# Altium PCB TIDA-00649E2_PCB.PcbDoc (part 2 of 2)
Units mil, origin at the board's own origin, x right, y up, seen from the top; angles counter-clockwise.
Board outline 3905 x 2600 mil, 2 copper layers (Top Layer, Bottom Layer), stack 62 mil thick; 120 components, 45 nets, 260 pads, 117 vias.
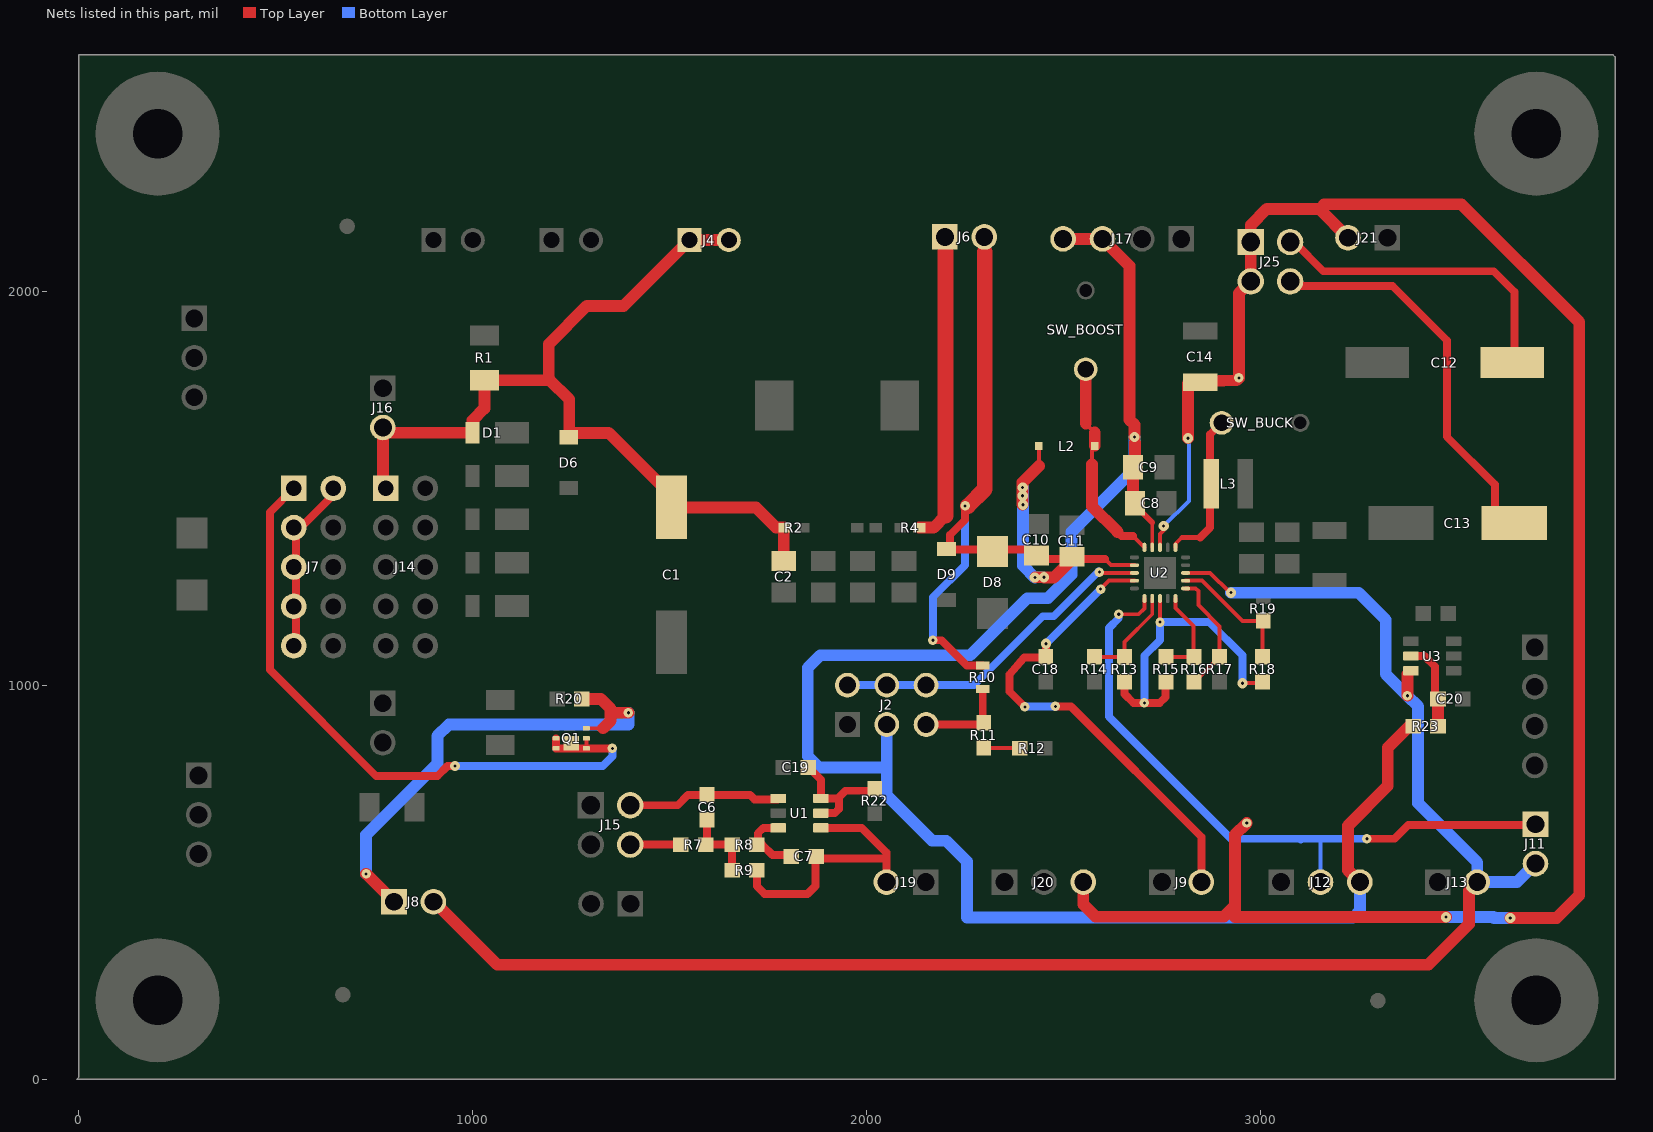
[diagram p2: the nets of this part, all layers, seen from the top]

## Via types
v1: diameter 24, hole 8, Top Layer to Bottom Layer, tented both sides, 66 vias
v2: diameter 26, hole 8, Top Layer to Bottom Layer, tented both sides, 47 vias
v3: diameter 19.68, hole 7.87, Top Layer to Bottom Layer, 4 vias

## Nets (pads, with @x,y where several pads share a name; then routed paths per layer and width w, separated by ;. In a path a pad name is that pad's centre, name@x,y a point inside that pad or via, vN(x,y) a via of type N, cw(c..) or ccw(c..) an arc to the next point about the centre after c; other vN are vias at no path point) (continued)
NetC6_1: C6.1 J15.2 U1.1 | length 389.2
  Top Layer w20: J15.2@1399.68,695 1520,695 1546.5,721.5 C6.1@1594.68,721.5 1703.5,721.5 1715,710 U1.1@1773.15,710
NetC6_2: C6.2 R7.2 R8.1 R9.1 | length 190
  Top Layer w10: R7.2@1594.68,598.5 R7.2@1598.19,595
  Top Layer w20: R7.2@1594.68,598.5 C6.2@1594.68,658.5 ; R7.2@1598.19,595 R8.1@1658.19,595 R9.1@1658.19,530
NetC7_1: C7.1 J19.2 R9.2 U1.4 | length 721.9
  Top Layer w20: R9.2@1721.18,530 1721.18,489.82 1741,470 1850,470 1870,490 1870,558.82 1871.18,560 2050,560 ; U1.4@1883.82,637.6 1987.4,637.6 2050,575 J19.2@2050,500
NetC7_2: C7.2 R8.2 U1.3 | length 185.3
  Top Layer w20: R8.2@1721.18,595 1735,595 1761,569 1799.19,569 C7.2@1808.19,560 ; R8.2@1723.68,597.5 1723.68,623.68 1737.6,637.6 U1.3@1775.55,637.6
NetC10_1: C10.1 C11.1 D8.1 D9.1 J6.2 L2.1 R10.1 U2.2 | length 2358.3
  Top Layer w10: 2437.13,1556.13 L2.1@2437.13,1607 L2.1@2437.13,1608 ; C11.1@2519.68,1317.68 C11.1@2519.68,1318.69 ; 2605,1320 2620.32,1304.68 U2.2@2679.72,1304.68
  Top Layer w20: v1(2168,1114) 2190,1114 2254,1050 R10.1@2294.68,1050 ; v1(2250,1455) 2250,1420 2212,1382 2212,1344 2412.71,1344 C10.1@2431,1325.71 ; C10.1@2413,1320 2605,1320
  Top Layer w30: v2@2396,1459 v2(2396,1481) v2(2396,1502) 2396,1515 2437.13,1556.13 ; v2@2428,1274 v2(2450,1274) ; v2@2450,1273 2475,1273 C11.1@2519.68,1317.68
  Top Layer w40: v1@2257,1455 2299.68,1497.68 2299.68,2100
  Bottom Layer w20: v1(2168,1114) 2168,1223.12 2250,1305.12 v1(2250,1455)
  Bottom Layer w30: v2@2397,1501 v2(2397,1458) 2397,1303 v2(2427,1273) 2428,1274 v2(2450,1274)
NetC12_1: C12.1 J25.2 | length 829.3
  Top Layer w20: J25.2@3075,2125 3085.43,2125 3159.43,2051 3592,2051 3644.26,1998.74 C12.1@3644.26,1791
NetC13_1: C13.1 J25.4 | length 1003.5
  Top Layer w20: J25.4@3075,2025 3087,2013 3335.37,2013 3473,1875.37 3473,1631 3595,1509 3595,1447.73 C13.1@3641.22,1401.51
NetC19_2: C19.2 R22.1 U1.5 U1.6 | length 319.7
  Top Layer w20: C19.2@1852.62,791.14 1883.82,759.94 U1.6@1883.82,712.4 1926.4,712.4 ; U1.5@1883.82,675 1919,675 1930,686 1930,712.4 1926.4,712.4 ; R22.1@2020.73,737.48 2015.24,732 1946,732 1926.4,712.4
NetC20_1: C20.1 R23.2 U3.5 | length 210.3
  Top Layer w20: U3.5@3381.87,1074 3416.31,1074 3442.5,1047.81 C20.1@3442.5,978
  Top Layer w30: R23.2@3450.5,896 C20.1@3450.5,965
NetJ2_2: J2.2 J2.4 J2.6 U2.3 | length 847.3
  Top Layer w10: v1@2593,1285 U2.3@2679.72,1285
  Bottom Layer w10: v1@2589,1289 v1(2591,1287)
  Bottom Layer w20: J2.2@1950.98,1000 J2.4@2050.98,1000 J2.6@2150.98,1000 2272,1000 2447,1175 2475,1175 v1@2589,1289
NetJ2_5: J2.5 R10.2 R11.2 | length 224.7
  Top Layer w20: J2.5@2150.98,900 R11.2@2292.5,900 ; R11.2@2294.68,906.81 R10.2@2294.68,990
NetJ7_1: J7.1 Q1.1 Q1.2 Q1.5 Q1.6 Q1.8 | length 1702.2
  Top Layer w10: Q1.1@1288.39,839.41 Q1.2@1288.39,865
  Top Layer w20: J7.1@545.68,1500 545.68,1499.68 485,1439 485,1039 755,769 910,769 936,795 v2(955,795) ; Q1.5@1211.62,865 Q1.6@1211.62,839.41 Q1.1@1288.39,839.41 v1(1354.41,839.41)
  Bottom Layer w20: v2(955,795) 1330,795 1354.41,819.41 v1(1354.41,839.41)
NetJ8_1: J8.1 Q1.3 R20.2 | length 1280.6
  Top Layer w10: Q1.3@1288.39,890.59 1330.59,890.59
  Top Layer w30: v1(729,521) J8.1@800,450 ; R20.2@1276.81,965 1325,965 1350,940 1350,930 ; 1330.59,890.59 1350,910 1350,930 ; v1(1395,930) 1350,930
  Bottom Layer w30: v1(729,521) 729,620 910,801 910,871 939,900 1395,900 v1(1395,930)
NetJ15_4: J15.4 R7.1 | length 128.5
  Top Layer w20: J15.4@1399.68,595 R7.1@1528.19,595
NetL2_2: L2.2 SW_BOOST.1 U2.20 | length 536.7
  Top Layer w10: 2556,1664 2578.87,1641.13 ; 2572,1561 2572,1601.13 L2.2@2578.87,1608 ; 2637,1389 2647,1379 ; 2676.28,1379 U2.20@2705.31,1349.96
  Top Layer w20: 2647,1379 2676.28,1379
  Top Layer w30: 2556,1664 SW_BOOST.1@2556,1802 ; 2572,1561 2572,1454 2637,1389 ; L2.2@2578.87,1608 2578.87,1641.13
NetL3_1: L3.1 SW_BUCK.1 U2.16 | length 392
  Top Layer w10: U2.16@2784.06,1349.96 2784.06,1359.06 2800,1375
  Top Layer w12: 2800,1375 2847,1375
  Top Layer w20: 2847,1375 2872,1400 2872,1637 SW_BUCK.1@2901,1666
NetR11_1: R11.1 R12.1 | length 90
  Top Layer w10: R11.1@2298.5,840 R12.1@2388.5,840
NFET: J7.2 J7.3 J7.5 J7.7 J7.9 | length 441.4
  Top Layer w20: J7.9@550.68,1110 550.68,1387.68 650.68,1487.68 J7.2@650.68,1510
OK_HYST: R15.1 R16.2 U2.10 | length 237.6
  Top Layer w10: R15.1@2760,1071.5 R16.2@2831.19,1071.5 ; U2.10@2784.06,1220.04 2784.06,1195.94 2830,1150 R16.2@2830,1072.68
OK_PROG: R16.1 R17.2 U2.11 | length 315.9
  Top Layer w10: U2.11@2809.65,1245.63 2835.37,1245.63 2842,1239 2842,1203 2896,1149 R17.2@2896,1071.5 2833.01,1008.5 R16.1@2831.19,1008.5
V_FILTER_OUT: J6.1 R4.2 | length 748.8
  Top Layer w30: R4.2@2133.31,1400 2170,1400 2200,1430
  Top Layer w40: 2200,1430 2200,2099.68
VBAT: C14.2 J20.3 J21.2 J25.1 J25.3 U2.18 | length 5097.9
  Top Layer w10: U2.18@2744.68,1349.96 2744.68,1383.68 2754,1393 v2(2754,1404) ; 3149,2209 3161,2221
  Top Layer w30: 2550,443 J20.3@2550,500 ; 2552,441 2581,412 2907,412 2935,440 ; v2(2816,1627) C14.2@2816,1766 ; C14.2@2847,1771.01 2939.04,1774.04 v1(2945,1780) 2945,1995 J25.3@2975,2025 J25.1@2975,2125 2975,2168 3016,2209 3149,2209 J21.2@3222,2136 ; v1(2965,650) 2935,620 2935,411 v2(3471,411) ; 3161,2221 3510,2221 3809,1922 3809,466 3752,409 v2(3634,409)
  Bottom Layer w10: v2(2754,1404) 2818,1468 v2@2818,1625
  Bottom Layer w30: v2(3471,411) 3591,411 3593,409 v2(3634,409)
VBAT_OK: J8.2 J11.2 J13.2 U2.13 U3.6 | length 4405.6
  Top Layer w10: U2.13@2809.65,1285 2872,1285 2922.16,1234.84 v2(2924.72,1234.84)
  Top Layer w30: J8.2@900,450 895,445 907,445 1062,290 3426,290 3529,393 3529,479 J13.2@3550,500 ; v1(3373,973) U3.6@3373,1027.73
  Bottom Layer w30: v2(2924.72,1234.84) 3249.16,1234.84 3318,1166 3318,1028 v1(3373,973) 3400,946 3400,700 3550,550 J13.2@3550,500 3651,500 J11.2@3698,547
VBAT_OV: R13.2 R14.1 U2.7 | length 254.2
  Top Layer w10: R14.1@2578.18,1071.5 R13.2@2654.68,1071.5 2654.68,1109.68 2725,1180 U2.7@2725,1220.04
VD: C1.1 C2.1 D1.2 D6.1 J4.1 J4.2 J14.1 J16.2 R1.1 R2.1 | length 2234.5
  Top Layer w30: J14.1@771.68,1504.31 J16.2@771.68,1654 ; J16.2@784.68,1641 D1.2@999.49,1641 999.49,1672.49 1029.68,1702.68 R1.1@1029.68,1773.91 1192.6,1773.91 1192.6,1866 1289.6,1963 1383,1963 J4.1@1550,2130 J4.2@1650,2130 ; 1194.68,1776 1244.68,1726 1244.68,1640.47 1344.53,1640.47 1504.68,1480.32 C1.1@1504.68,1451.26 1718.74,1451.26 1770,1400 R2.1@1791.38,1400 ; C2.1@1789.68,1315 R2.1@1789.68,1398.31
VOUT_EN: J11.1 J12.2 U2.6 | length 1762.2
  Top Layer w10: v1(2640,1180) 2690,1180 2705,1195 2705,1219.72 U2.6@2705.31,1220.04 U2.6@2705.31,1209.25
  Top Layer w20: v1(3270,610) 3340,610 3375,645 J11.1@3696,645
  Bottom Layer w10: v1@2640,1170 v1(2640,1180) ; 3100,610 3147,610 3152.2,604.8 J12.2@3152.2,500
  Bottom Layer w20: v1@2640,1170 2615,1145 2615,920 2925,610 3100,610 3102,608 3104,610 v1(3270,610)
VOUT_SET: R18.1 R19.2 U2.12 | length 331.2
  Top Layer w10: U2.12@2809.65,1265.31 2851.68,1265.31 2903.44,1213.56 2953.99,1163.01 R19.2@3005,1163.01 ; R18.1@3005,1071.5 R19.2@3005,1163.01 ; R19.2@3007,1163.01 R19.2@3005,1163.01
VRDIV: R13.1 R15.2 R18.2 U2.8 | length 832.5
  Top Layer w10: v1(2744.68,1160) U2.8@2744.68,1220.04 ; v2(2954,1005) R18.2@3001.5,1005
  Top Layer w20: R13.1@2654.68,1008.5 2654.68,977.32 2677,955 v1(2705,955) 2744,955 2759,970 R15.2@2759,1007.5
  Bottom Layer w20: v1(2705,955) 2705,1074.63 2744.68,1114.32 v1(2744.68,1160) 2870,1160 2954,1076 v2(2954,1005)
VREF_SAMP: C18.1 J9.2 U2.4 | length 1233.8
  Top Layer w10: v1(2594,1244) 2615.31,1265.31 U2.4@2679.72,1265.31
  Top Layer w20: v1(2401.57,944.88) 2362.2,984.25 2362.2,1027.2 2400,1070 C18.1@2453.19,1070 ; C18.1@2455,1071.81 v2(2455,1105) ; v1(2479,946) 2518.57,946 2849.68,614.88 J9.2@2849.68,500
  Bottom Layer w20: v1(2401.57,944.88) 2402.69,946 v1(2479,946) ; v2(2455,1105) v1(2594,1244)
VSTOR: C8.1 C9.1 J2.3 J12.3 J17.3 J17.4 R23.1 U2.19 | length 4702.8
  Top Layer w10: U2.19@2725,1349.96 2725,1413
  Top Layer w15: C8.1@2676,1462 2725,1413
  Top Layer w30: J17.4@2498.68,2133 J17.3@2598.68,2133 2667,2064.68 2667,1674 2680,1661 v2(2680,1630) ; C9.1@2674,1542 C9.1@2676,1544 ; C8.1@2675.31,1448.54 C8.1@2676,1447.85 ; C8.1@2676,1462 C9.1@2676,1544 ; C9.1@2676,1553 C9.1@2676,1544 ; C9.1@2681,1553 2681,1616 ; J12.3@3252.2,500 3222,530.19 3222,643 3323,744 3323,841.5 3377.5,896 R23.1@3387.5,896
  Bottom Layer w30: J2.3@2050.98,900 2050.98,791.14 ; v2(2680,1630) 2680,1549 2519.68,1388.68 2519.68,1280.16 2460,1220.47 2407.47,1220.47 2263,1076 1882,1076 1850.39,1044.39 1850.39,819.61 1878.86,791.14 2050.98,791.14 ; J12.3@3252.2,500 3252.2,427.19 3235,410 2255,410 2255,552 2202,605 2166,605 2050.98,720.02 2050.98,791.14
pads on no net: FID1.1 FID2.1 FID3.1 H1.1 H2.1 H3.1 H4.1 Q1.0 SH-J1.0 SH-J2.0 SH-J3.0 SH-J4.0 SH-J5.0 SH-J6.0 SH-J7.0 SH-J8.0 SH-J9.0 SH-J10.0 SH-J12.0 SH-J14.0 SH-J16.0 SH-J20.0 SH-J22.0 SH-J25.0 U3.3

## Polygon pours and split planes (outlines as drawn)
DJT on Bottom Layer "Bottom Layer-No Net 1" (solid, remove dead copper, pour order 1): 1305,1125 1295,1115 1270,1115 1260,1105 1260,1070 1275,1055 1295,1055 1325,1085 1325,1090 1325,1120
DJT on Bottom Layer "Bottom Layer-No Net" (solid, remove dead copper, pour order 0): 1320,1405 1300,1405 1270,1435 1270,1445 1270,1450 1295,1475 1315,1475 1335,1455 1335,1420
GND on Bottom Layer "BOTTOM_LAYER_GND_P002" (solid, remove dead copper, pour order 2): -5,0 3900,0 3900,2600 0,2600 0,0
DJT on Top Layer "Top Layer-No Net 1" (solid, remove dead copper, pour order 14): 1260,1060 1260,1105 1270,1115 1310,1115 1320,1105 1320,1085 1320,1080 1285,1045 1275,1045
DJT on Top Layer "Top Layer-No Net" (solid, remove dead copper, pour order 12): 1270,1455 1270,1435 1295,1410 1320,1410 1330,1420 1330,1460 1315,1475 1285,1475
LOOP- on Top Layer "TOP_LAYER_LOOP-_P010" (solid, remove dead copper, pour order 10): 340,1282 192,1282 193,531 220,504 241,483 305,483 364,483 403,522 405,524 405,886 405,907 340,972
GND on Top Layer "TOP_LAYER_GND_P004" (solid, remove dead copper, pour order 4): 2381.25,2225.12 2383.25,2223.12 3411.25,2223.12 3411.25,1244.12 3413.25,1242.12 3413.9,1241.47 3413.9,1067.94 2469.13,1075.24 2360.25,1184.12 2360.25,2204.12
GND on Top Layer "TOP_LAYER_GND_P006" (solid, remove dead copper, pour order 6): 1477.16,1272.82 3095.16,1272.82 3100.16,1267.82 3100.16,1106.82 1651,1105 1584,1002 1410,1002 1410.16,1192.82 1410.16,1272.82
"LOOP +" on Top Layer "TOP_LAYER_LOOP_+_P008" (solid, remove dead copper, pour order 8): 194,1332.16 194,1616 194,1620 194,1960 234,2000 236,2002 350,2002 361,2002 381,1982 381,1957 380,1623 379.98,1616 353,1596 353,1525 353,1461 337,1338

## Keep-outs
Keep-Out Layer:
  text ".Layer_Name" at 577,-858.49 h30

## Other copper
Top Layer:
  pour cut-out: 3250,2100 3360,2100 3360,2190 3380,2190 3380,2075 3250,2075
  text ".Layer_Name" at 577,-858.49 h30
Bottom Layer:
  pour cut-out: 1890,941.5 1909.49,941.5 1909.49,860 2020,860 2020,825 1890,825
  pour cut-out: 495.48,1171.01 8.01,1171.01 8,1171 9,1170 9,1109 11,1111 495,1111
  pour cut-out: 1819,891 1407,891 1396.97,880.97 1396.97,830.74 1817.26,830.74 1819,829
  pour cut-out: 2241,380 2231,380 2231,25.49 2269,26 2283.91,25.49 2280,380
  text ".Layer_Name" at 577,-858.49 h30

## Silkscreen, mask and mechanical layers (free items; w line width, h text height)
Top Overlay:
  region: 2225,265 1925,265 1925,165 2225,165
  text "VBAT" at 3151,2225 h50
  text "GND" at 3305,2225 h50
  text "3V3" at 1207,2213 h70
  text "VD" at 1559,2209 h70
  text "GND" at 883,2208 h70
  text "GND" at 2699,2205 h72.83
  text "VSTOR" at 2430,2203 h72.83
  text "2" at 3069,2202 h50
  text "1" at 2890,2122 h50
  text "3" at 2885,2015 h50
  text "4" at 3146,2010 h50
  text "Loop+" at 377,1918 h100
  text "2" at 640,1568 h50
  text "9" at 813,1008 h50
  text "10" at 890,1006 h50
  text "9" at 543,1005 h50
  text "10" at 627,1003 h50
  text "GND" at 3812,977 h72.83 r90
  text "95%" at 2125,798 h50
  text "50%" at 1913,795 h50
  text "80%" at 2015,795 h50
  text "VOUT" at 3816,747 h72.83 r90
  text "1" at 1210,722 h50
  text "2" at 1471,721 h50
  text "GND" at 2760,580 h50 r90
  text "GND" at 3444,577 h50 r90
  text "VREF" at 2873,574 h50 r90
  text "GND" at 2362,573 h50 r90
  text "GND" at 3060,572 h50 r90
  text "EN" at 2466,566 h50 r90
  text "VBAT" at 2573,565 h50 r90
  text "VOUT_EN" at 3180,565 h50 r90
  text "VSTOR" at 3252,563 h50 r90
  text "GND" at 2180,562 h50 r90
  text "VBAT_OK" at 3546,562 h50 r90
  text "3" at 1202,549 h50
  text "4" at 1462,547 h50
  text "Loop-" at 368,539 h100
  text "VShunt" at 1953,398 h60
  text "'.PRJ_Number'.PCB_Rev-" at 1280,188 h100
  text ".Layer_Name" at 577,-858.49 h30
Bottom Overlay:
  text ".Layer_Name" at 577,-858.49 h30
Top Paste:
  text ".Layer_Name" at 577,-858.49 h30
Bottom Paste:
  text ".Layer_Name" at 577,-858.49 h30
Top Solder:
  text ".Layer_Name" at 577,-858.49 h30
  text ".Layer_Name" at 577,-858.49 h30
Bottom Solder:
  rectangle: 1583,783.98 1628,829.98
  rectangle: 1581,891.98 1626,937.98
  rectangle: 229,1064.98 274,1110.98
  rectangle: 229,1171.98 274,1217.98
  rectangle: 2281,226.98 2326,272.98
  rectangle: 2186,223.98 2231,269.98
  text ".Layer_Name" at 577,-858.49 h30
Drill Guide:
  text ".Layer_Name" at 577,-858.49 h30
M1 Board Outline:
  lines w10: 0,0 0,2600 3900,2600 3900,0 5,0
  text ".Layer_Name" at 577,-858.49 h30
M2 Board Dimensions:
  rectangle: 0,-275 125,-150
  rectangle: 125,-400 500,-275
  lines w7: 0,-275 1000,-275 ; 125,-400 125,-150 ; 250,-400 250,-150 ; 500,-400 500,-150 ; 750,-400 750,-150 ; 0,-400 1000,-400 1000,-150 0,-150 0,-400
  text ".Layer_Name" at 577,-858.49 h30
M3 3D STEP Top:
  text ".Layer_Name" at 577,-858.49 h30
M4 3D STEP Bottom:
  text ".Layer_Name" at 577,-858.49 h30
M5 Assembly Top:
  lines w10: -292,-930.17 6308,-930.17 ; -292,-726.83 6310,-726.83 ; -292,-523.5 -292,-1133.5 3713,-1133.5 6310,-1133.5 6310,-523.5 -291.5,-523.5 -291.5,-1133.5 1284,-1133.5 ; 2173,-1133.5 2173,-523.5 ; 3440,-726.83 3440,-523.5 ; 4280,-726.83 4280,-523.5 ; 4902,-1140 4902,-937.17
  text "COMPONENTS MARKED 'DNP' SHOULD NOT BE POPULATED." at 1153.5,-318.5 h30
  text "ASSEMBLY VARIANT:" at 1153,-434 h30
  text ".VariantName" at 2189,-434 h30
  text "PCB VIEWED FROM TOP SIDE" at -228.5,-655.67 h30
  text "BOARD #:" at 2248,-655.67 h30
  text ".PRJ_Number" at 2793.5,-655.67 h30
  text "REV:" at 3638,-655.67 h30
  text ".PCB_Rev" at 3929.5,-655.67 h30
  text "SVN REV:" at 4476,-655.67 h30
  text ".VersionControl_RevNumber" at 4982,-655.67 h30
  text "TID #:" at 2248,-859 h30
  text ".TID" at 2793.5,-859 h30
  text "PLOT NAME =" at -228.5,-1064.34 h30
  text ".plot_File_Name" at 577,-1064.34 h30
  text "GENERATED    :" at 2250,-1064.34 h30
  text ".Print_Date" at 3119.5,-1064.34 h30
  text ".Print_Time" at 3848.5,-1064.34 h30
  text "TEXAS INSTRUMENTS" at 5113,-1064.34 h30
M6 Assembly Bottom:
  lines w10: -292.5,-727.33 6309.5,-727.33 ; -290.5,-930.67 6309.5,-930.67 ; 1115.5,-1140.5 1115.5,-937.67 ; 1737.5,-727.33 1737.5,-524 ; 2577.5,-727.33 2577.5,-524 ; 3844.5,-1134 3844.5,-524 ; 4733.5,-1134 6309,-1134 6309,-524 -292.5,-524 -292.5,-1134 2304.5,-1134 6309.5,-1134 6309.5,-524
  text "COMPONENTS MARKED 'DNP' SHOULD NOT BE POPULATED." at 6102,-318 h30
  text ".VariantName" at 5058,-434 h30
  text "ASSEMBLY VARIANT:" at 6097,-434 h30
  text ".VersionControl_RevNumber" at 1035.5,-656.17 h30
  text "SVN REV:" at 1541.5,-656.17 h30
  text ".PCB_Rev" at 2088,-656.17 h30
  text "REV:" at 2379.5,-656.17 h30
  text ".PRJ_Number" at 3224,-656.17 h30
  text "BOARD #:" at 3769.5,-656.17 h30
  text "PCB VIEWED FROM BOTTOM SIDE" at 6246,-656.17 h30
  text ".TID" at 3224,-859.5 h30
  text "TID #:" at 3769.5,-859.5 h30
  text "TEXAS INSTRUMENTS" at 904.5,-1064.84 h30
  text ".Print_Time" at 2169,-1064.84 h30
  text ".Print_Date" at 2898,-1064.84 h30
  text "GENERATED    :" at 3767.5,-1064.84 h30
  text ".plot_File_Name" at 5440.5,-1064.84 h30
  text "PLOT NAME =" at 6246,-1064.84 h30
M9 Title Sheet:
  drawing of 57 lines, arcs and shapes, not listed
  text "1" at 739.84,8036.5 h30
  text "2" at 3235.5,8036.5 h30
  text "3" at 5724.84,8036.5 h30
  text "4" at 8231.51,8036.5 h30
  text "5" at 10730.5,8036.5 h30
  text "6" at 13235.5,8036.5 h30
  text "A" at -416.5,6893.5 h30
  text "A" at 14383.5,6893.5 h30
  text "B" at -416.5,4513.5 h30
  text "B" at 14383.5,4513.5 h30
  text "C" at -416.5,2138.5 h30
  text "C" at 14383.5,2138.5 h30
  text "PROJECT TITLE:" at 11343.5,277.5 h30
  text ".PRJ_Title" at 11393.5,144.17 h30
  text "DESIGNED FOR:" at 11343.5,-23.5 h30
  text ".PRJ_Customer" at 11393.5,-163.5 h30
  text "D" at -416.5,-231.5 h30
  text "D" at 14383.5,-231.5 h30
  text "FILE NAME:" at 11343.5,-323.5 h30
  text ".PCB_File_Name_No_Path" at 11393.5,-443.5 h30
  text "Texas Instruments (TI) and/or its licensors do not warrant the accuracy or completeness of this specification" at 6374,-605.34 h30
  text "ENGINEER:" at 11343.5,-613.5 h30
  text "LAYOUT BY:" at 12848.5,-613.5 h30
  text "or any information contained therein. TI and/or its licensors do not warrant that this design will meet" at 6329.01,-718 h30
  text ".PRJ_Engineer" at 11393.5,-768.49 h30
  text ".PCB_Layout" at 12899,-768.49 h30
  text "the specifications, will be suitable for your application or fit for any particular purpose, or will operate in" at 6329.01,-830.67 h30
  text ".Layer_Name" at 577,-858.49 h30
  text "ALTIUM DESIGNER VERSION:" at 12848.5,-923.5 h30
  text "an implementation. TI and/or its licensors do not warrant that the design is production worthy. You should" at 6329.01,-943.33 h30
  text "completely validate and test your design implementation to confirm the system functionality for your application." at 6374,-1056 h30
  text ".print_Scale" at 11393.5,-1056.83 h30
  text ".Application_BuildNumber" at 12899,-1056.83 h30
  text "1" at 739.84,-1263.5 h30
  text "2" at 3235.5,-1263.5 h30
  text "3" at 5724.84,-1263.5 h30
  text "4" at 8231.51,-1263.5 h30
  text "5" at 10730.5,-1263.5 h30
  text "6" at 13235.5,-1263.5 h30
M10 Fab Notes:
  drawing of 173 lines, arcs and shapes, not listed
  text "DESIGN INFORMATION" at 12378.02,6201 h30
  text "MIN. TRACK WIDTH:" at 11733.46,6021 h30
  text "6" at 12829.7,6021 h30
  text "MIL" at 12984.46,6021 h30
  text "MIN. CLEARANCE:" at 11733.46,5889 h30
  text "0.15" at 12769.7,5889 h30
  text "mm" at 12984.46,5889 h30
  text "MIN. VIA PAD SIZE:" at 11733.46,5757 h30
  text "24" at 12799.71,5757 h30
  text "MIL" at 12984.46,5757 h30
  text "0.05mm (2MIL)" at 12428.46,5615.29 h30
  text "MINIMUM ANNULAR RING" at 11404.23,5611 h30
  text "EXTERNAL" at 13136.46,5611 h30
  text "PER" at 11604.23,5493 h30
  text "IPC-D-275 CLASS 2 LEVEL C" at 11824.23,5493 h30
  text "MIL, HOLES" at 13312.46,5380.71 h30
  text "+/-" at 12920,5380 h30
  text "+/-" at 13774,5380 h30
  text "REGISTRATION TOLERANCES:" at 11404.23,5375 h30
  text "METAL" at 12604,5375 h30
  text "5" at 13180.2,5375 h30
  text "3" at 14013.2,5375 h30
  text "MIL" at 14129.46,5375 h30
  text "+/-" at 13774,5262 h30
  text "HOLE SIZE TOLERANCE (UNLESS OTHERWISE SPECIFIED):" at 11404.23,5257 h30
  text "3" at 14013.2,5257 h30
  text "MIL" at 14129.46,5257 h30
  text "MATERIAL:" at 11329.46,5047.54 h30
  text "FR-4 High Tg" at 12315.9,4907.21 h30
  text "FR-408" at 11750.46,4898.64 h30
  text "OTHER" at 13238.46,4898.64 h30
  text "X" at 12161,4895 h30
  text "62 MIL (1.6mm) +/-10%" at 12070.56,4735.92 h30
  text "THICKNESS:" at 11404.23,4731.64 h30
  text "X" at 11942.4,4731.64 h30
  text "OTHER" at 13355.46,4731.64 h30
  text "TOLERANCE:" at 11404.23,4573.64 h30
  text "X" at 12243.53,4573.64 h30
  text "ANSI IPC-6012 TYPE 3 CLASS 2" at 12430.48,4573.64 h30
  text "OTHER +/-" at 12430.46,4417.64 h30
  text "BOW & TWIST:" at 11404.23,4260.64 h30
  text "X" at 12243.53,4260.64 h30
  text "ANSI IPC-6012 TYPE 3 CLASS 2" at 12430.48,4260.64 h30
  text "OTHER +/-" at 12430.46,4102.13 h30
  text "DRILLING:" at 11329.46,3963.64 h30
  text "REFERENCE:" at 11404.23,3846.64 h30
  text "X" at 12052.46,3846.64 h30
  text "AS SHOWN" at 12239.46,3846.64 h30
  text "X" at 12953.46,3846.64 h30
  text "NC_DRILL FILES" at 13090.46,3846.64 h30
  text "PTH COPPER THICKNESS:" at 11404.23,3688.64 h30
  text "X" at 12534.46,3688.64 h30
  text "20-30 um" at 12671.46,3688.64 h30
  text "OTHER" at 13388.46,3688.64 h30
  text "BOARD FINISH:" at 11329.46,3529.64 h30
  text "SILKSCREEN:" at 11484.68,3411.64 h30
  text "X" at 12433.46,3411.64 h30
  text "TOP" at 12559.46,3411.64 h30
  text "BOTTOM" at 13070.46,3411.64 h30
  text "SILKSCREEN COLOR:" at 11484.68,3244.64 h30
  text "X" at 12432.42,3244.64 h30
  text "WHITE" at 12559.46,3244.64 h30
  text "OTHER" at 13070.46,3244.64 h30
  text "X" at 12563.42,3085.44 h30
  text "GREEN" at 12690.46,3085.44 h30
  text "OTHER" at 13308.46,3085.44 h30
  text "SOLDER RESIST COLOR:" at 11484.68,3074.64 h30
  text "X" at 12563.42,2915.44 h30
  text "MATTE" at 12690.46,2915.44 h30
  text "SEMI-GLOSS" at 13308,2914.8 h30
  text "IMMERSION GOLD (ENIG)" at 12390.46,2726.92 h30
  text "ENEPIG" at 13728,2723.64 h30
  text "SURFACE FINISH:" at 11329.46,2722.64 h30
  text "X" at 12203.51,2722.64 h30
  text "IMM. TIN/SILVER OR EQUIV" at 11659,2565.64 h30
  text "OTHER" at 13090.46,2565.64 h30
  text "ARRAY/PANEL:" at 11329.46,2386.64 h30
  text "CUT AND TRIM PER M1 BOARD OUTLINE" at 12390.46,2382.35 h30
  text "N.C. ROUTE" at 12390.46,2230.64 h30
  text "X" at 13069.46,2230.64 h30
  text "V. SCORE" at 13256.46,2230.64 h30
  text "CERTIFICATION:" at 11329.46,2093.64 h30
  text "MATERIALS AND WORKMANSHIP FOR ALL PCBS" at 12054.46,2093.64 h30
  text "TO MEET OR EXCEED THE REQUIREMENTS OF:" at 12054.46,1995.64 h30
  text "X" at 11680.96,1859.13 h30
  text "ANSI IPC-A-600F CLASS ->" at 11819.96,1859.13 h30
  text "X" at 13459.02,1859.13 h30
  text "2" at 13577.96,1859.14 h30
  text "1" at 13262.96,1857.64 h30
  text "3" at 13931.96,1857.64 h30
  text "X" at 12495.02,1699.64 h30
  text "RoHS" at 12631.96,1699.64 h30
  text "OTHER" at 13276.36,1699.64 h30
  text "PER ORDER" at 13673.42,1699.64 h30
  text "ALL BOARDS MUST MEET OR EXCEED UL94-V0 REQUIREMENTS." at 11357,1534 h30
  text "PCB MUST BEAR THE UL94V-0 UL REGISTERED MATERIAL ID NUMBER" at 11357,1414 h30
  text "ADDITIONAL REQUIREMENTS:" at 11329.46,1240.64 h30
  text "MICROSECTION:" at 11404.23,1125.64 h30
  text "YES" at 12309.96,1125.64 h30
  text "REQUIRED" at 13171.46,969.49 h30
  text "BARE BOARD ELEC. TEST:" at 11404.23,966.64 h30
  text "NONE" at 12709.96,966.64 h30
  text "X" at 13044.46,966.64 h30
  text "PER ORDER" at 13763.46,966.64 h30
  text ".Layer_Name" at 577,-858.49 h30
M11 Gerber Information:
  lines w10: -292,-930.17 6308,-930.17 ; -292,-726.83 6310,-726.83 ; -292,-523.5 -292,-1133.5 3713,-1133.5 6310,-1133.5 6310,-523.5 -291.5,-523.5 -291.5,-1133.5 1284,-1133.5 ; 2173,-1133.5 2173,-523.5 ; 3440,-726.83 3440,-523.5 ; 4280,-726.83 4280,-523.5 ; 4902,-1140 4902,-937.17
  text "ALL ARTWORK VIEWED FROM TOP SIDE" at -228.5,-655.67 h30
  text "BOARD #:" at 2248,-655.67 h30
  text ".PRJ_Number" at 2793.5,-655.67 h30
  text "REV:" at 3638,-655.67 h30
  text ".PCB_Rev" at 3929.5,-655.67 h30
  text "SVN REV:" at 4476,-655.67 h30
  text ".VersionControl_RevNumber" at 4982,-655.67 h30
  text "LAYER NAME =" at -228.5,-858.49 h30
  text "TID #:" at 2248,-859 h30
  text ".TID" at 2793.5,-859 h30
  text "PLOT NAME =" at -228.5,-1064.34 h30
  text ".plot_File_Name" at 577,-1064.34 h30
  text "GENERATED    :" at 2250,-1064.34 h30
  text ".Print_Date" at 3119.5,-1064.34 h30
  text ".Print_Time" at 3848.5,-1064.34 h30
  text "TEXAS INSTRUMENTS" at 5113,-1064.34 h30
M12 Stackup:
  drawing of 191 lines, arcs and shapes, not listed
  text "Layer" at 9815,7865 h60
  text "Name" at 10224.91,7865 h60
  text "Material" at 11154.66,7865 h60
  text "Thickness" at 12014.42,7865 h60
  text "Constant" at 12664.26,7865 h60
  text "Board Layer Stack" at 13234.12,7865 h60
  text "1" at 9815,7745 h60
  text "Top Overlay" at 10224.91,7745 h60
  text "2" at 9815,7625 h60
  text "Top Solder" at 10224.91,7625 h60
  text "Solder Resist" at 11154.66,7625 h60
  text "0.40mil" at 12014.42,7625 h60
  text "3.5" at 12664.26,7625 h60
  text "3" at 9815,7505 h60
  text "Top Layer" at 10224.91,7505 h60
  text "Copper" at 11154.66,7505 h60
  text "1.40mil" at 12014.42,7505 h60
  text "4" at 9815,7385 h60
  text "Dielectric1" at 10224.91,7385 h60
  text "FR-4" at 11154.66,7385 h60
  text "59.20mil" at 12014.42,7385 h60
  text "4.8" at 12664.26,7385 h60
  text "5" at 9815,7265 h60
  text "Bottom Layer" at 10224.91,7265 h60
  text "Copper" at 11154.66,7265 h60
  text "1.40mil" at 12014.42,7265 h60
  text "6" at 9815,7145 h60
  text "Bottom Solder" at 10224.91,7145 h60
  text "Solder Resist" at 11154.66,7145 h60
  text "0.40mil" at 12014.42,7145 h60
  text "3.5" at 12664.26,7145 h60
  text "7" at 9815,7025 h60
  text "Bottom Overlay" at 10224.91,7025 h60
  text ".Layer_Name" at 577,-858.49 h30
M13 Component Bodies Top:
  text ".Layer_Name" at 577,-858.49 h30
M14 Component Bodies Bottom:
  text ".Layer_Name" at 577,-858.49 h30
M15 Courtyards Top:
  text ".Layer_Name" at 577,-858.49 h30
M16 Courtyards Bottom:
  text ".Layer_Name" at 577,-858.49 h30
Drill Drawing:
  circle w10: c5318.96,2929.03 r11.05
  lines w10: 5307.91,2973.23 5313.43,2973.23 5318.96,2967.7 5324.48,2973.23 5330.01,2973.23 5324.48,2978.75 5330.01,2984.28 5324.48,2984.28 5318.96,2989.8 5313.43,2984.28 5307.91,2984.28 5313.43,2978.75 5307.91,2973.23 ; 5307.91,3017.42 5330.01,3017.42 5330.01,3039.52 5307.91,3039.52 5307.91,3017.42 ; 5307.91,3067.15 5318.96,3072.67 5330.01,3067.15 5324.48,3078.19 5330.01,3089.24 5318.96,3083.72 5307.91,3089.24 5313.43,3078.19 5307.91,3067.15 ; 5307.91,3116.87 5330.01,3116.87 5330.01,3138.97 5307.91,3138.97 5307.91,3116.87 ; 5307.91,3172.11 5313.43,3172.11 5313.43,3166.59 5324.48,3166.59 5324.48,3172.11 5330.01,3172.11 5330.01,3183.16 5324.48,3183.16 5324.48,3188.69 5313.43,3188.69 5313.43,3183.16 5307.91,3183.16 5307.91,3172.11 ; 5307.91,3238.41 5330.01,3238.41 5318.96,3216.31 5307.91,3238.41 ; 5307.91,3277.08 5318.96,3266.03 5330.01,3277.08 5318.96,3288.13 5307.91,3277.08 ; 5307.91,3315.75 5318.96,3321.28 5330.01,3315.75 5324.48,3326.8 5330.01,3337.85 5318.96,3332.33 5307.91,3337.85 5313.43,3326.8 5307.91,3315.75 ; 5307.91,3371 5313.43,3371 5318.96,3365.47 5324.48,3371 5330.01,3371 5324.48,3376.52 5330.01,3382.05 5324.48,3382.05 5318.96,3387.57 5313.43,3382.05 5307.91,3382.05 5313.43,3376.52 5307.91,3371 ; 5312.33,2975.44 5315.64,2975.44 5318.96,2972.12 5322.27,2975.44 5325.59,2975.44 5322.27,2978.75 5325.59,2982.07 5322.27,2982.07 5318.96,2985.38 5315.64,2982.07 5312.33,2982.07 5315.64,2978.75 5312.33,2975.44 ; 5312.33,3121.29 5325.59,3121.29 5325.59,3134.55 5312.33,3134.55 5312.33,3121.29 ; 5312.33,3320.17 5318.96,3323.49 5325.59,3320.17 5322.27,3326.8 5325.59,3333.43 5318.96,3330.12 5312.33,3333.43 5315.64,3326.8 5312.33,3320.17
  lines w12: 5286,2903.06 6841.45,2903.06 ; 5286,3400.28 6841.45,3400.28 ; 5443.74,2853.34 5443.74,3450 ; 5602.27,2853.34 5602.27,3450 ; 5913.09,2853.34 5913.09,3450 ; 6035.2,2853.34 6035.2,3450 ; 6215.31,2853.34 6215.31,3450 ; 6569.43,2853.34 6569.43,3450 ; 5286,2853.34 6841.45,2853.34 6841.45,3450 5286,3450 5286,2853.34
  text "Symbol" at 5315.83,3415.19 h36
  text "Quantity" at 5458.65,3415.19 h36
  text "Finished Hole Size" at 5617.19,3415.19 h36
  text "Plated" at 5928.01,3415.19 h36
  text "Hole Type" at 6050.12,3415.19 h36
  text "Drill Layer Pair" at 6230.23,3415.19 h36
  text "Hole Tolerance" at 6584.35,3415.19 h36
  text "4" at 5458.65,3365.47 h30
  text "7.87mil (0.200mm)" at 5617.19,3365.47 h30
  text "PTH" at 5928.01,3365.47 h30
  text "Round" at 6050.12,3365.47 h30
  text "Top Layer - Bottom Layer" at 6230.23,3365.47 h30
  text "113" at 5458.65,3315.75 h30
  text "8.00mil (0.203mm)" at 5617.19,3315.75 h30
  text "PTH" at 5928.01,3315.75 h30
  text "Round" at 6050.12,3315.75 h30
  text "Top Layer - Bottom Layer" at 6230.23,3315.75 h30
  text "2" at 5458.65,3266.03 h30
  text "32.00mil (0.813mm)" at 5617.19,3266.03 h30
  text "PTH" at 5928.01,3266.03 h30
  text "Round" at 6050.12,3266.03 h30
  text "Top Layer - Bottom Layer" at 6230.23,3266.03 h30
  text "20" at 5458.65,3216.31 h30
  text "40.00mil (1.016mm)" at 5617.19,3216.31 h30
  text "PTH" at 5928.01,3216.31 h30
  text "Round" at 6050.12,3216.31 h30
  text "Top Layer - Bottom Layer" at 6230.23,3216.31 h30
  text "6" at 5458.65,3166.59 h30
  text "40.94mil (1.040mm)" at 5617.19,3166.59 h30
  text "PTH" at 5928.01,3166.59 h30
  text "Round" at 6050.12,3166.59 h30
  text "Top Layer - Bottom Layer" at 6230.23,3166.59 h30
  text "2" at 5458.65,3116.87 h30
  text "42.00mil (1.067mm)" at 5617.19,3116.87 h30
  text "PTH" at 5928.01,3116.87 h30
  text "Round" at 6050.12,3116.87 h30
  text "Top Layer - Bottom Layer" at 6230.23,3116.87 h30
  text "6" at 5458.65,3067.15 h30
  text "43.31mil (1.100mm)" at 5617.19,3067.15 h30
  text "PTH" at 5928.01,3067.15 h30
  text "Round" at 6050.12,3067.15 h30
  text "Top Layer - Bottom Layer" at 6230.23,3067.15 h30
  text "40" at 5458.65,3017.42 h30
  text "45.28mil (1.150mm)" at 5617.19,3017.42 h30
  text "PTH" at 5928.01,3017.42 h30
  text "Round" at 6050.12,3017.42 h30
  text "Top Layer - Bottom Layer" at 6230.23,3017.42 h30
  text "8" at 5458.65,2967.7 h30
  text "47.24mil (1.200mm)" at 5617.19,2967.7 h30
  text "PTH" at 5928.01,2967.7 h30
  text "Round" at 6050.12,2967.7 h30
  text "Top Layer - Bottom Layer" at 6230.23,2967.7 h30
  text "4" at 5458.65,2917.98 h30
  text "125.98mil (3.200mm)" at 5617.19,2917.98 h30
  text "PTH" at 5928.01,2917.98 h30
  text "Round" at 6050.12,2917.98 h30
  text "Top Layer - Bottom Layer" at 6230.23,2917.98 h30
  text "205 Total" at 5458.65,2868.26 h30
  text ".Layer_Name" at 577,-858.49 h30
M17 Embedded Cavity:
  text ".Layer_Name" at 577,-858.49 h30
M18 Embedded Assembly:
  text ".Layer_Name" at 577,-858.49 h30
M19 Embedded Keepout:
  text ".Layer_Name" at 577,-858.49 h30

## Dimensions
0,-400 to 1000,-400 on M2 Board Dimensions
0,0 to 3895,2600 on M2 Board Dimensions
0,0 to 3900,0 on M2 Board Dimensions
